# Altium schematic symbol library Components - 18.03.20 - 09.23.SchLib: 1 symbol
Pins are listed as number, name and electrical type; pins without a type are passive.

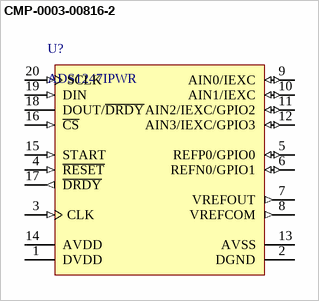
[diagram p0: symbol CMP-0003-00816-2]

## CMP-0003-00816-2
designator U?, comment ADS1247IPWR
Low Noise, Precision 24-Bit ADC, -40 to 105 degC, 20-pin SOP (PW20), Green (RoHS & no Sb/Br); Manufacturer: Texas Instruments; Interface: Serial SPI; Analog Voltage AV/DD(Max)(V): 5.25; SubFamily: Precision ADC (<=10MSPS); Resolution(Bits): 24; Architecture: Delta-Sigma; Digital Supply(Min)(V): 2.7; # Input Channels: 3; Sample Rate (max)(SPS): 2k
footprint TI-PW20_N (SOP, 20-Leads, Body 6.5x4.4mm, Pitch 0.65mm, IPC Medium Density)
footprint TI-PW20_M (SOP, 20-Leads, Body 6.5x4.4mm, Pitch 0.65mm, IPC Low Density)
footprint TI-PW20_L (SOP, 20-Leads, Body 6.5x4.4mm, Pitch 0.65mm, IPC High Density)
pins: 1 DVDD (power) "Digital power supply", 2 DGND (power) "Digital ground", 3 CLK (in) "External clock input. Tie this pin to DGND to activate the internal oscillator.", 4 ~{RESET} (in) "Chip reset (active low). Returns all register values to reset values.", 5 REFP0/GPIO0 (io), 6 REFN0/GPIO1 (io), 7 VREFOUT (out) "Positive internal reference voltage output", 8 VREFCOM (out) "Negative internal reference voltage output. Connect this pin to AVSS when using a unipolar supply, or to the midvoltage of the power supply when using a bipolar supply.", 9 AIN0/IEXC (io), 10 AIN1/IEXC (io), 11 AIN2/IEXC/GPIO2 (io), 12 AIN3/IEXC/GPIO3 (io), 13 AVSS (power) "Negative analog power supply", 14 AVDD (power) "Positive analog power supply", 15 START (in) "Conversion start. See text for description of use.", 16 ~{CS} (in) "Chip select (active low)", 17 ~{DRDY} (out) "Data ready (active low)", 18 DOUT/~{DRDY} (hiz), 19 DIN (in) "Serial data input", 20 SCLK (in) "Serial clock input"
